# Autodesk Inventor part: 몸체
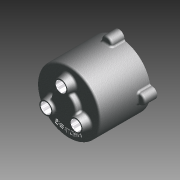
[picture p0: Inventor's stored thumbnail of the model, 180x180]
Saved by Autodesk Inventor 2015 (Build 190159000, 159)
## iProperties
Created: 2012-05
Part Number: 몸체
Document SubType Name: 모델링
Designer: SeoGD™
Material: 알루미늄 6061
Appearance: 알루미늄 - 평지
Mass: 473.798 g
Surface Area: 687.661 cm^2
Volume: 175.481 cm^3
Density: 2.7 g/cm^3
변환 표준: STEP AP214IS
파일 이름: C:\Users\SeoGD\Desktop\?쒗뿕\紐몄껜.stp
전처리기: Build: 253, Release: 2010 SP1 - Date: Wed 07/29/2009
전송 단위: 밀리미터
불확실성: 0.01
Author: SeoGD™
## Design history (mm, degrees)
sketch "스케치2"
  geometry: C1 r 50 at (0, 0); 1 further point
  constraints: 1 centre point, 1 coincident
  dimensions: "d9" = 100 diameter of C1
extrude "돌출2" new body sketch "스케치2" distance "d10" = 80; taper "d11" = 0 deg
feature "쉘1" dims "d12" = 5
sketch "스케치3" dims "d13" = 55
  geometry: C1 r 7.5 at (0, 27.5); C2 r 12.5 at (0, 27.5); 2 further points
  constraints: 2 centre point, 2 coincident, 2 vertical alignment, 2 other
  dimensions: "d14" = 15 diameter of C1; "d15" = 25 diameter of C2
extrude "돌출3" join sketch "스케치3" distance "d16" = 12; taper "d17" = -10 deg
hole "구멍2" diameter "d20" = 15; stored, may be unused: countersink angle "d24" = 90 deg, drill point angle "d26" = 118 deg; dims "d18" = 10, "d19" = 10, "d21" = 6, "d22" = 4, "d23" = 2, "d25" = 15
chamfer "모따기1" distance "d27" = 1; stored, may be unused: second distance "d28" = 2, angle "d29" = 45 deg
sketch "스케치4"
  geometry: L1 (0, 0)-(0, 88); L2 (0, 70)-(13.16, 70); L3 (-45, 75)-(45, 75) reference; L4 (-50, 80)-(50, 80) reference; L5 (13.16, 70)-(14.5, 75); L6 (20, 80)-(20, 88); L7 (20, 88)-(0, 88); L8 (20, 80)-(14.5, 75)
  constraints: 12 end point, 3 point on line, 2 perpendicular, 1 vertical
  dimensions: "d34" = 40 diameter of L6 L1; "d35" = 105 deg angle of L5 L3; "d36" = 5 distance between parallel lines of L2 L3; "d37" = 8 distance between parallel lines of L7 L4; "d51" = 29 diameter of L5.end L1
revolve "회전1" sketch "스케치4" stored, may be unused: angle "d38" = 90 deg
hole "구멍3" diameter "d41" = 15; stored, may be unused: countersink angle "d45" = 90 deg, drill point angle "d47" = 0 deg; dims "d39" = 10, "d40" = 10, "d42" = 6, "d43" = 22, "d44" = 13, "d46" = 15
chamfer "모따기2" distance "d48" = 1; stored, may be unused: second distance "d49" = 2, angle "d50" = 45 deg
fillet "모깎기1" dims "d52" = 3
fillet "모깎기2" dims "d53" = 3, "d72" = 0.2
sketch "스케치5"
  geometry: A1 r 50 centre (0, 0) between (50, 0) and (-8.074, 49.344) reference; A2 r 8.5 centre (0, 52) between (8.074, 49.344) and (-8.074, 49.344); 1 further point
  constraints: 5 point on circle, 1 centre point, 1 horizontal alignment
  dimensions: "d54" = 90 deg dimension on point (0, 0) A2.centre A1.start; "d55" = 52 distance of A2.centre point (0, 0); "d56" = 17 diameter of A2
extrude "돌출4" join sketch "스케치5" distance "d57" = 20; taper "d58" = 0 deg
fillet "모깎기3" dims "d59" = 3
hole "구멍4" diameter "d62" = 4.134; stored, may be unused: countersink angle "d66" = 90 deg, drill point angle "d68" = 118 deg; dims "d60" = 10, "d61" = 10, "d63" = 12, "d64" = 22, "d65" = 13, "d67" = 15
sketch "스케치6"
  geometry: C1 r 47 at (0, 0) reference; C2 r 42.5 at (0, 0); 1 further point
  constraints: 1 centre point, 1 coincident, 1 other
  dimensions: "d73" = 85 diameter of C2
feature "엠보싱1" sketch "스케치6" dims "d74" = 1, "d75" = 0
node "솔리드1"
node "솔리드 본체"
node "곡면 본체"
pattern_circular "원형 패턴1" dims "d31" = 360 deg
pattern_circular "원형 패턴2" dims "d70" = 360 deg
node "솔리드2"
